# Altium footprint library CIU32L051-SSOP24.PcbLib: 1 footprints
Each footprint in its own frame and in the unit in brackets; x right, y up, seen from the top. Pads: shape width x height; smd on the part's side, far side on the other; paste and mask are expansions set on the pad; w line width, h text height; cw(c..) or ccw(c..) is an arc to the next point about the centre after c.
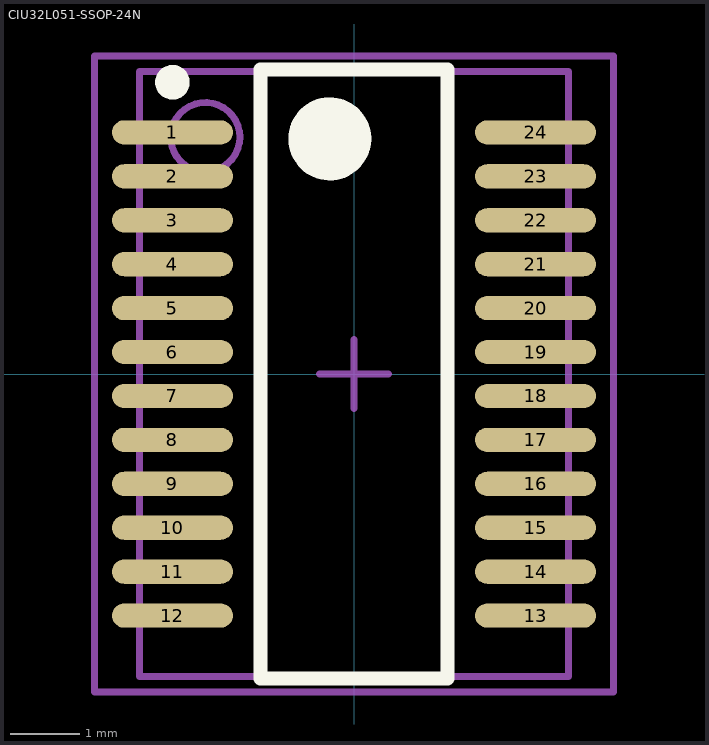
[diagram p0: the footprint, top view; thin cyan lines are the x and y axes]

## CIU32L051-SSOP-24N [mm] "SOP, 24-Leads, Body 8.8x6.2mm (max), Pitch 0.63mm, IPC Medium Density"
height 1.75
pads (24):
  oval 1.75x0.35 smd: 1(-2.625,3.492) 2(-2.625,2.857) 3(-2.625,2.222) 4(-2.625,1.587) 5(-2.625,0.953) 6(-2.625,0.318) 7(-2.625,-0.318) 8(-2.625,-0.953) 9(-2.625,-1.587) 10(-2.625,-2.222) 11(-2.625,-2.857) 12(-2.625,-3.492) 13(2.625,-3.492) 14(2.625,-2.857) 15(2.625,-2.222) 16(2.625,-1.587) 17(2.625,-0.953) 18(2.625,-0.318) 19(2.625,0.318) 20(2.625,0.953) 21(2.625,1.587) 22(2.625,2.222) 23(2.625,2.857) 24(2.625,3.492)
Top Overlay:
  circle w0.6: c-0.35,3.4 r0.3
  circle w0.25: c-2.625,4.217 r0.125
  lines w0.2: -1.35,-4.4 1.35,-4.4 1.35,4.4 -1.35,4.4 -1.35,-4.4
Mechanical 13:
  circle w0.1: c-2.15,3.425 r0.5
  lines w0.1: -3.1,-4.375 3.1,-4.375 3.1,4.375 -3.1,4.375 -3.1,-4.375
Mechanical 15:
  lines w0.1: -0.5,0 0.5,0 ; 0,-0.5 0,0.5 ; -3.75,-4.6 3.75,-4.6 3.75,4.6 -3.75,4.6 -3.75,-4.6
3D body: height 1.75, standoff 0.1, extent -3.1,-4.375 3.1,4.375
